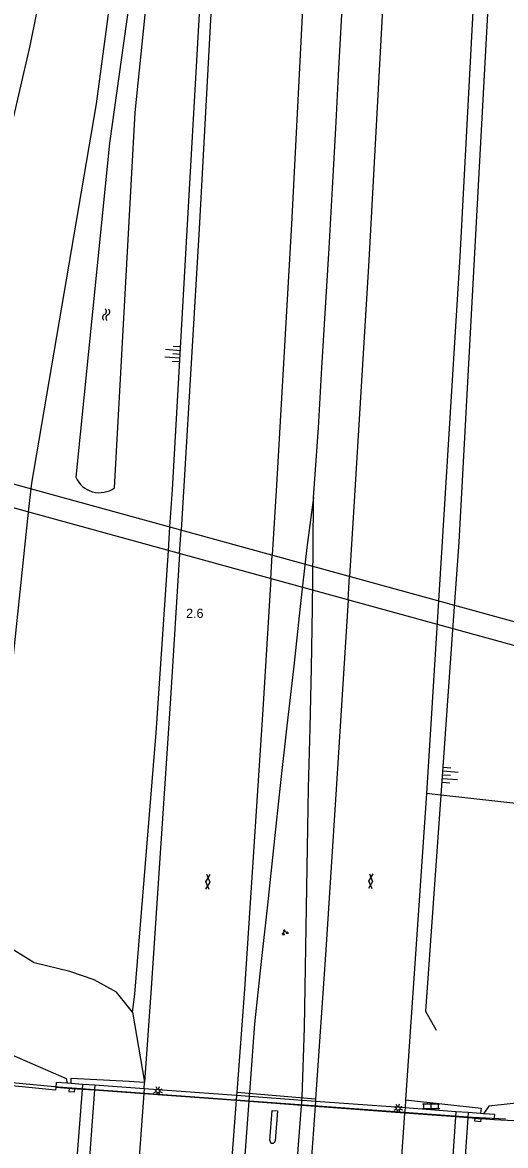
# Model space of a CAD drawing. Extents: x 133000 to 136000, y 400500 to 403500.
# Drawn here: x 133097.3 to 133161.8, y 401055.6 to 401205.6 of the extents above; entities that cross this region are included whole.
import ezdxf

# ---------------------------------------------------------------- set-up
doc = ezdxf.new("R2010")
doc.units = 0
for name, color, linetype in [('gg-bbg-pilaar viaduct of brug', 7, 'Continuous'), ('gg-knt-BGT kruinlijn', 7, 'Continuous'), ('gg-knt-bovenkant onderkant talud', 7, 'Continuous'), ('gg-knt-verharding', 7, 'Continuous'), ('gg-knt-verharding nz', 7, 'Continuous'), ('gg-kntw-bovenkant insteek waterloop', 7, 'Continuous'), ('gg-kwrk-duiker nz vlak', 7, 'Continuous'), ('gg-kwrk-kunstwerk', 7, 'Continuous'), ('gg-kwrk-kunstwerk niveau 01', 7, 'Continuous'), ('gt-anno-nummer hm paal', 7, 'Continuous'), ('gt-grn-groengrens', 7, 'Continuous'), ('gt-knt-geleideconstructie', 7, 'Continuous'), ('gt-symb-gesloten verharding', 7, 'Continuous'), ('gt-symb-groenvak', 7, 'Continuous'), ('gt-symb-klinker verharding', 7, 'Continuous'), ('gt-symb-kolk', 7, 'Continuous'), ('gt-symb-kolk center center', 7, 'Continuous'), ('gt-symb-lichtmast', 7, 'Continuous'), ('gt-symb-talud symbool', 7, 'Continuous'), ('gt-symb-watersymbool', 7, 'Continuous')]:
    doc.layers.add(name, color=color, linetype=linetype)

# ---------------------------------------------------------------- blocks, each defined once
blk = doc.blocks.new('gt0-KOLKCC')
at = {"layer": 'gt-symb-kolk center center'}
blk.add_lwpolyline([(-0.38, 0.2), (0.38, 0.2), (0.38, -0.2), (-0.38, -0.2)], close=True, dxfattribs=at)
blk = doc.blocks.new('gt0-LMAST')
at = {"layer": 'gt-symb-lichtmast'}
for p, q in [((-0.18, 0.17), (-0.45, 0.44)), ((-0.01, 0.25), (-0.01, 0.62)), ((0.17, 0.17), (0.44, 0.44)), ((-0.26, 0), (-0.63, 0)), ((-0.18, -0.18), (-0.45, -0.45)), ((-0.01, -0.25), (-0.01, -0.63)), ((0.44, -0.45), (0.17, -0.18)), ((0.24, 0), (0.62, 0))]:
    blk.add_line(p, q, dxfattribs=at)
blk.add_circle((-0.01, 0), 0.25, dxfattribs=at)
blk = doc.blocks.new('gt0-KL1')
at = {"layer": 'gt-symb-klinker verharding'}
for p, q in [((-1.15, 0.3), (1.15, 0.3)), ((-1, -0.3), (-1, 0.3)), ((-0.5, 0.3), (-0.5, 0.45)), ((0, -0.3), (0, 0.3)), ((0.5, 0.3), (0.5, 0.45)), ((1, -0.3), (1, 0.3)), ((-1.15, -0.3), (1.15, -0.3)), ((-0.5, -0.45), (-0.5, -0.3)), ((0.5, -0.45), (0.5, -0.3))]:
    blk.add_line(p, q, dxfattribs=at)
blk = doc.blocks.new('gt0-GRVAK')
at = {"layer": 'gt-symb-groenvak'}
for p, q in [((-0.11, 0.19), (-0.23, 0.24)), ((-0.18, 0.15), (0.09, 0.15)), ((-0.09, 0.21), (-0.16, 0.32)), ((-0.05, 0.21), (-0.05, 0.39)), ((0, 0.21), (0.06, 0.32)), ((0.01, 0.19), (0.13, 0.24)), ((0.26, -0.05), (0.2, 0.06)), ((0.3, -0.05), (0.3, 0.13)), ((0.35, -0.05), (0.41, 0.06)), ((-0.25, -0.23), (-0.36, -0.18)), ((-0.32, -0.26), (-0.05, -0.26)), ((-0.23, -0.21), (-0.29, -0.1)), ((-0.18, -0.2), (-0.18, -0.02)), ((-0.14, -0.21), (-0.07, -0.1)), ((-0.12, -0.23), (0, -0.18)), ((0.24, -0.07), (0.12, -0.02)), ((0.17, -0.11), (0.44, -0.11)), ((0.37, -0.07), (0.49, -0.02))]:
    blk.add_line(p, q, dxfattribs=at)
blk = doc.blocks.new('gt0-KOLK')
at = {"layer": 'gt-symb-kolk'}
blk.add_lwpolyline([(0, 0), (0.38, 0), (0.38, 0.4), (-0.37, 0.4), (-0.37, 0), (0, 0)], dxfattribs=at)
blk = doc.blocks.new('gt0-WA')
at = {"layer": 'gt-symb-watersymbool'}
for centre, start, end in [((-0.32, 0.02), 28.0725, 151.9275), ((0.43, 0.42), 208.0725, 331.9275), ((-0.32, -0.43), 28.0725, 151.9275), ((0.43, -0.03), 208.0725, 331.9275)]:
    blk.add_arc(centre, 0.425, start, end, dxfattribs=at)
blk = doc.blocks.new('gt0-TALUD_1')
at = {"layer": 'gt-symb-talud symbool'}
for p, q in [((-1, -1), (-1, 0)), ((0.5, -2), (0.5, 0)), ((-0.5, -2), (-0.5, 0)), ((0, -1), (0, 0)), ((1, -1), (1, 0))]:
    blk.add_line(p, q, dxfattribs=at)
blk = doc.blocks.new('gt0-GESVH1')
at = {"layer": 'gt-symb-gesloten verharding'}
for p, q in [((-0.99, -0.26), (0.01, 0.24)), ((0.01, -0.26), (-0.99, 0.24)), ((0.01, 0.24), (1.01, -0.26)), ((1.01, 0.24), (0.01, -0.26))]:
    blk.add_line(p, q, dxfattribs=at)

msp = doc.modelspace()

# ---------------------------------------------------------------- linework, layer by layer
at = {"layer": 'gg-bbg-pilaar viaduct of brug'}
msp.add_lwpolyline([(133130.36, 401056.31), (133130.64, 401060.31), (133131.35, 401060.26), (133131.07, 401056.26)], dxfattribs=at)
msp.add_arc((133130.71, 401056.29), 0.357, 178.0113, 355.2463, dxfattribs=at)
at = {"layer": 'gg-knt-BGT kruinlijn'}
msp.add_line((133116.8, 401135.08), (133117.01, 401138.24), dxfattribs=at)
for points in [[(133117.01, 401138.24), (133117.34, 401143.23), (133119.28, 401177.07), (133121.35, 401213.83), (133124.17, 401268.5)], [(133086.08, 401146.75), (133086.45, 401149.08), (133091.38, 401172.65), (133098.33, 401202.51), (133101.76, 401219.51), (133102.76, 401229.74), (133107.55, 401244.75)], [(133111.99, 401073.45), (133112.31, 401075.84), (133115.18, 401110.76), (133116.8, 401135.08)], [(133081.11, 401081.59), (133083.92, 401077.36), (133088.45, 401072.41), (133094.13, 401068.5), (133103.15, 401064.59), (133103.29, 401063.95)], [(133168.14, 401061.81), (133159.61, 401060.87), (133158.89, 401059.88)]]:
    msp.add_lwpolyline(points, dxfattribs=at)
at = {"layer": 'gg-knt-bovenkant onderkant talud'}
for p, q in [((133098.14, 401140.22), (133098.47, 401143.34)), ((133154.87, 401126.37), (133153.17, 401102.42)), ((133148.48, 401061.72), (133148.4, 401060.65))]:
    msp.add_line(p, q, dxfattribs=at)
for points in [[(133166.67, 401260.17), (133162.81, 401248.19), (133160.97, 401242.67), (133159.46, 401207.62), (133157.61, 401174), (133155.57, 401136.19), (133154.87, 401126.37)], [(133098.47, 401143.34), (133098.55, 401144.08), (133107.18, 401194.73), (133110.77, 401221.43), (133109.57, 401225.49), (133112.57, 401241.16)], [(133111.99, 401073.45), (133109.88, 401076.1), (133106.89, 401077.75), (133103.64, 401078.89), (133098.86, 401080.01), (133094.76, 401082.59), (133093.15, 401086.62), (133093.7, 401098.51), (133098.14, 401140.22)], [(133153.17, 401102.42), (133151.12, 401073.58), (133152.57, 401071.02)]]:
    msp.add_lwpolyline(points, dxfattribs=at)
at = {"layer": 'gg-knt-verharding'}
for p, q in [((133118.3, 401134.67), (133118.5, 401137.83)), ((133130.49, 401131.31), (133130.68, 401134.49)), ((133140.8, 401128.48), (133141, 401131.65)), ((133152.78, 401126.95), (133151.26, 401102.63)), ((133151.26, 401102.63), (133148.48, 401061.72)), ((133113.55, 401063.2), (133113.62, 401064.09)), ((133125.93, 401062.7), (133125.9, 401062.3)), ((133136.46, 401061.81), (133125.93, 401062.7)), ((133136.46, 401061.81), (133136.44, 401061.52))]:
    msp.add_line(p, q, dxfattribs=at)
for points in [[(133125.46, 401268.27), (133124.63, 401249.62), (133122.79, 401212.56), (133120.89, 401178.03), (133118.87, 401143.69), (133118.5, 401137.83)], [(133137.62, 401266.09), (133136.81, 401248.4), (133133.24, 401178.67), (133131.24, 401143.82), (133130.68, 401134.49)], [(133148.14, 401264.2), (133147.21, 401243.51), (133145.51, 401209.88), (133143.56, 401173.81), (133141.45, 401138.74), (133141, 401131.65)], [(133160.1, 401262.05), (133159.2, 401242.69), (133157.48, 401207.91), (133155.7, 401174.36), (133152.78, 401126.95)], [(133118.3, 401134.67), (133117.08, 401115.31), (133114.49, 401076.65), (133113.62, 401064.09)], [(133130.49, 401131.31), (133129.43, 401113.88), (133126.96, 401076.51), (133125.93, 401062.7)], [(133140.8, 401128.48), (133139.18, 401102.51), (133137.83, 401081.75), (133136.46, 401061.81)], [(133101.77, 401063.39), (133101.73, 401063.03), (133092.31, 401063.96)], [(133103.82, 401063.91), (133103.83, 401064.61), (133111.58, 401064.22), (133113.62, 401064.09)], [(133148.48, 401061.72), (133158.55, 401060.62), (133158.5, 401059.91)], [(133175.29, 401058.36), (133168.24, 401058.65), (133160.3, 401059.08)]]:
    msp.add_lwpolyline(points, dxfattribs=at)
at = {"layer": 'gg-knt-verharding nz'}
for p, q in [((133113.55, 401063.2), (133112.47, 401048.13)), ((133125.9, 401062.3), (133124.78, 401047.24)), ((133136.44, 401061.52), (133135.33, 401046.47)), ((133148.4, 401060.65), (133148.35, 401059.96)), ((133148.35, 401059.96), (133147.37, 401046.31))]:
    msp.add_line(p, q, dxfattribs=at)
at = {"layer": 'gg-kntw-bovenkant insteek waterloop'}
msp.add_lwpolyline([(133109.61, 401143.46), (133112.38, 401193.59), (133116.38, 401232.74), (133115.01, 401232.76), (133108.93, 401189.49), (133104.44, 401144.89)], dxfattribs=at)
msp.add_arc((133107.6, 401146.24), 3.43, 203.1695, 305.9024, dxfattribs=at)
at = {"layer": 'gg-kwrk-duiker nz vlak'}
for p, q in [((133036.16, 401160.48), (133216.5, 401110.88)), ((133215.72, 401107.86), (133035.21, 401157.53))]:
    msp.add_line(p, q, dxfattribs=at)
at = {"layer": 'gg-kwrk-kunstwerk'}
for p, q in [((133103.82, 401063.91), (133103.29, 401063.95)), ((133105.37, 401063.8), (133103.82, 401063.91)), ((133106.97, 401063.68), (133105.89, 401048.61)), ((133155.2, 401060.15), (133154.12, 401045.1)), ((133160.3, 401059.08), (133156.8, 401059.34)), ((133158.5, 401059.91), (133156.85, 401060.03)), ((133158.89, 401059.88), (133158.5, 401059.91))]:
    msp.add_line(p, q, dxfattribs=at)
for points in [[(133103.29, 401063.95), (133101.8, 401064.06), (133101.77, 401063.39)], [(133105.32, 401063.13), (133103.92, 401063.21), (133101.77, 401063.39)], [(133160.3, 401059.08), (133160.38, 401059.77), (133158.89, 401059.88)]]:
    msp.add_lwpolyline(points, dxfattribs=at)
at = {"layer": 'gg-kwrk-kunstwerk niveau 01'}
for p, q in [((133105.32, 401063.13), (133105.37, 401063.8)), ((133106.97, 401063.68), (133105.37, 401063.8)), ((133113.55, 401063.2), (133106.97, 401063.68)), ((133104.29, 401049.43), (133105.32, 401063.13)), ((133106.92, 401063.03), (133105.32, 401063.13)), ((133113.51, 401062.54), (133106.92, 401063.03)), ((133125.86, 401061.63), (133113.51, 401062.54)), ((133125.9, 401062.3), (133113.55, 401063.2)), ((133136.44, 401061.52), (133125.9, 401062.3)), ((133136.39, 401060.85), (133125.86, 401061.63)), ((133148.35, 401059.96), (133136.39, 401060.85)), ((133148.4, 401060.65), (133136.44, 401061.52)), ((133155.2, 401060.15), (133148.4, 401060.65)), ((133155.15, 401059.46), (133148.35, 401059.96)), ((133156.8, 401059.34), (133155.15, 401059.46)), ((133156.85, 401060.03), (133155.2, 401060.15)), ((133156.8, 401059.34), (133155.79, 401045.7)), ((133156.85, 401060.03), (133156.8, 401059.34))]:
    msp.add_line(p, q, dxfattribs=at)
at = {"layer": 'gt-grn-groengrens'}
for p, q in [((133153.17, 401102.42), (133151.26, 401102.63)), ((133189.3, 401098.43), (133153.17, 401102.42)), ((133111.99, 401073.45), (133113.62, 401064.09))]:
    msp.add_line(p, q, dxfattribs=at)
at = {"layer": 'gt-knt-geleideconstructie'}
for points in [[(133136.2, 401142.19), (133136.85, 401151.49), (133137.31, 401159.51), (133137.77, 401167.52), (133138.29, 401175.46), (133138.72, 401183.46), (133139.15, 401191.45), (133139.58, 401199.44), (133140.01, 401207.44)], [(133136.2, 401142.19), (133135.27, 401135.5), (133134.39, 401127.61), (133133.54, 401119.63), (133132.61, 401111.67), (133131.73, 401103.7), (133130.9, 401095.78), (133130.02, 401087.79), (133129.14, 401079.8), (133128.28, 401071.9), (133127.71, 401063.97), (133124.55, 401021.46), (133123.98, 401013.38), (133123.47, 401004.09), (133123.19, 400997.4), (133122.76, 400989.44), (133122.51, 400980.1), (133122.33, 400973.42), (133122.15, 400965.47), (133121.79, 400953.49), (133121.55, 400946.79), (133121.64, 400943.07)], [(133121.64, 400943.07), (133122.52, 400949.39), (133123.4, 400955.96), (133124.51, 400963.88), (133125.52, 400971.82), (133126.49, 400979.78), (133127.53, 400987.7), (133128.51, 400995.62), (133129.55, 401003.6), (133130.59, 401011.52), (133131.52, 401020.89), (133134.65, 401062.08), (133134.98, 401071.33), (133135.12, 401079.39), (133135.26, 401087.44), (133135.39, 401095.41), (133135.53, 401103.39), (133135.72, 401111.42), (133135.92, 401119.42), (133136.03, 401127.39), (133136.15, 401135.36), (133136.2, 401142.19)], [(133095.46, 401064.09), (133102.08, 401063.47), (133157.41, 401059.43), (133161.82, 401059.18)]]:
    msp.add_lwpolyline(points, dxfattribs=at)

# ---------------------------------------------------------------- block references
at = {"layer": 'gt-symb-gesloten verharding', "rotation": -93.89789623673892}
for p in [(133143.84, 401090.93), (133122.08, 401090.85)]:
    msp.add_blockref('gt0-GESVH1', p, dxfattribs=at)
at = {"layer": 'gt-symb-groenvak'}
msp.add_blockref('gt0-GRVAK', (133132.35, 401084.08), dxfattribs=at)
at = {"layer": 'gt-symb-klinker verharding'}
msp.add_blockref('gt0-KL1', (133151.89, 401060.89), dxfattribs=at)
at = {"layer": 'gt-symb-kolk', "rotation": 175.5837165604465}
msp.add_blockref('gt0-KOLK', (133103.92, 401063.21), dxfattribs=at)
at = {"layer": 'gt-symb-kolk center center', "rotation": -3.897896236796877}
msp.add_blockref('gt0-KOLKCC', (133158.11, 401059.04), dxfattribs=at)
at = {"layer": 'gt-symb-lichtmast', "rotation": 161.27513193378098}
for p in [(133115.39, 401062.93), (133147.46, 401060.6)]:
    msp.add_blockref('gt0-LMAST', p, dxfattribs=at)
at = {"layer": 'gt-symb-talud symbool'}
for p, xscale, yscale, rotation in [((133118.38, 401161.32), 0.999968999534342, 0.9999689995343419, -94.41628344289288), ((133153.46, 401105.11), 1.000451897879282, 1.000451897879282, 85.98782884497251)]:
    msp.add_blockref('gt0-TALUD_1', p, dxfattribs=dict(at, xscale=xscale, yscale=yscale, rotation=rotation))
at = {"layer": 'gt-symb-watersymbool', "rotation": 84.20389934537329}
msp.add_blockref('gt0-WA', (133108.48, 401166.53), dxfattribs=at)

# ---------------------------------------------------------------- texts
at = {"layer": 'gt-anno-nummer hm paal'}
msp.add_text('2.6', height=1.25, dxfattribs=at).set_placement((133119.17, 401126.08))

doc.saveas('drawing.dxf')
